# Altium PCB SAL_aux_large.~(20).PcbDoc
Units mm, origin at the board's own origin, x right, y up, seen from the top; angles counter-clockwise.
Board outline 62 x 80 mm, 2 copper layers (Top Layer, Bottom Layer); 36 components, 48 nets, 158 pads, 6 vias.
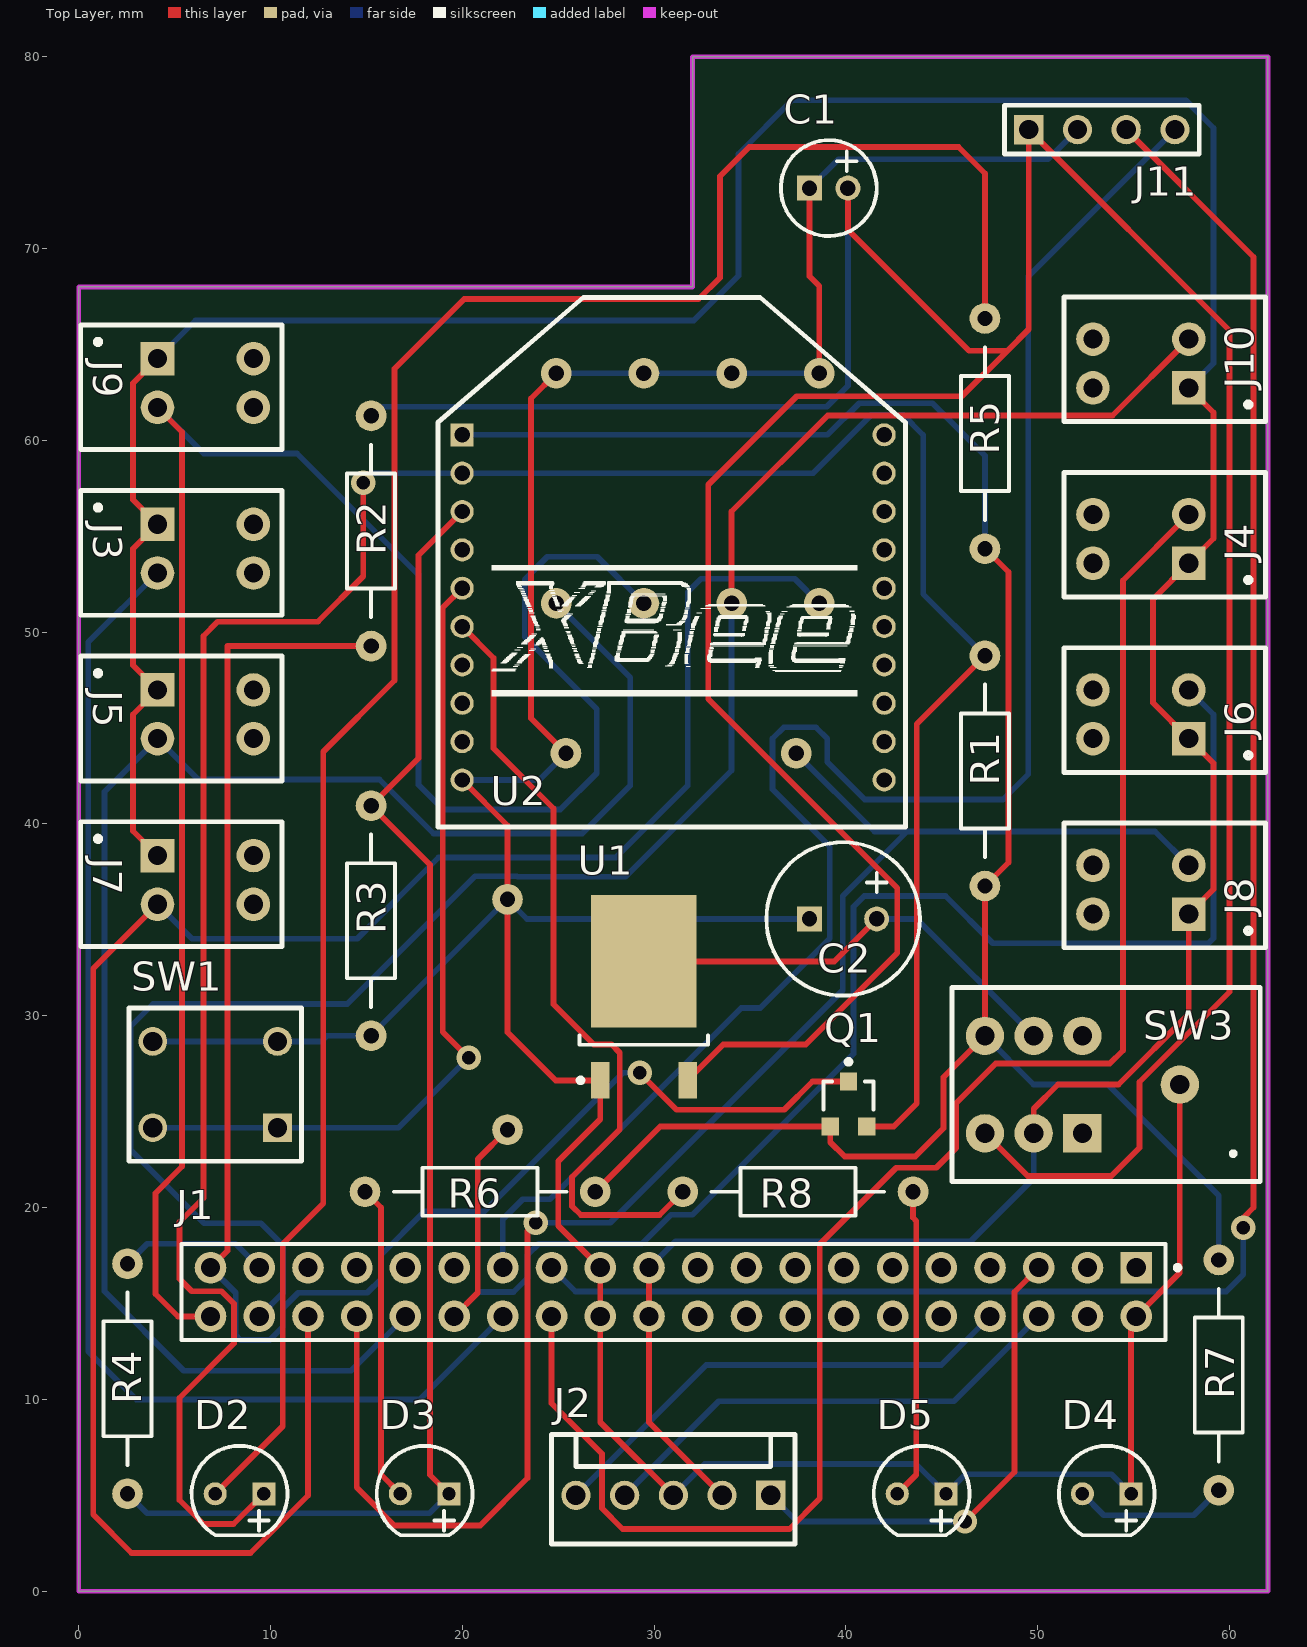
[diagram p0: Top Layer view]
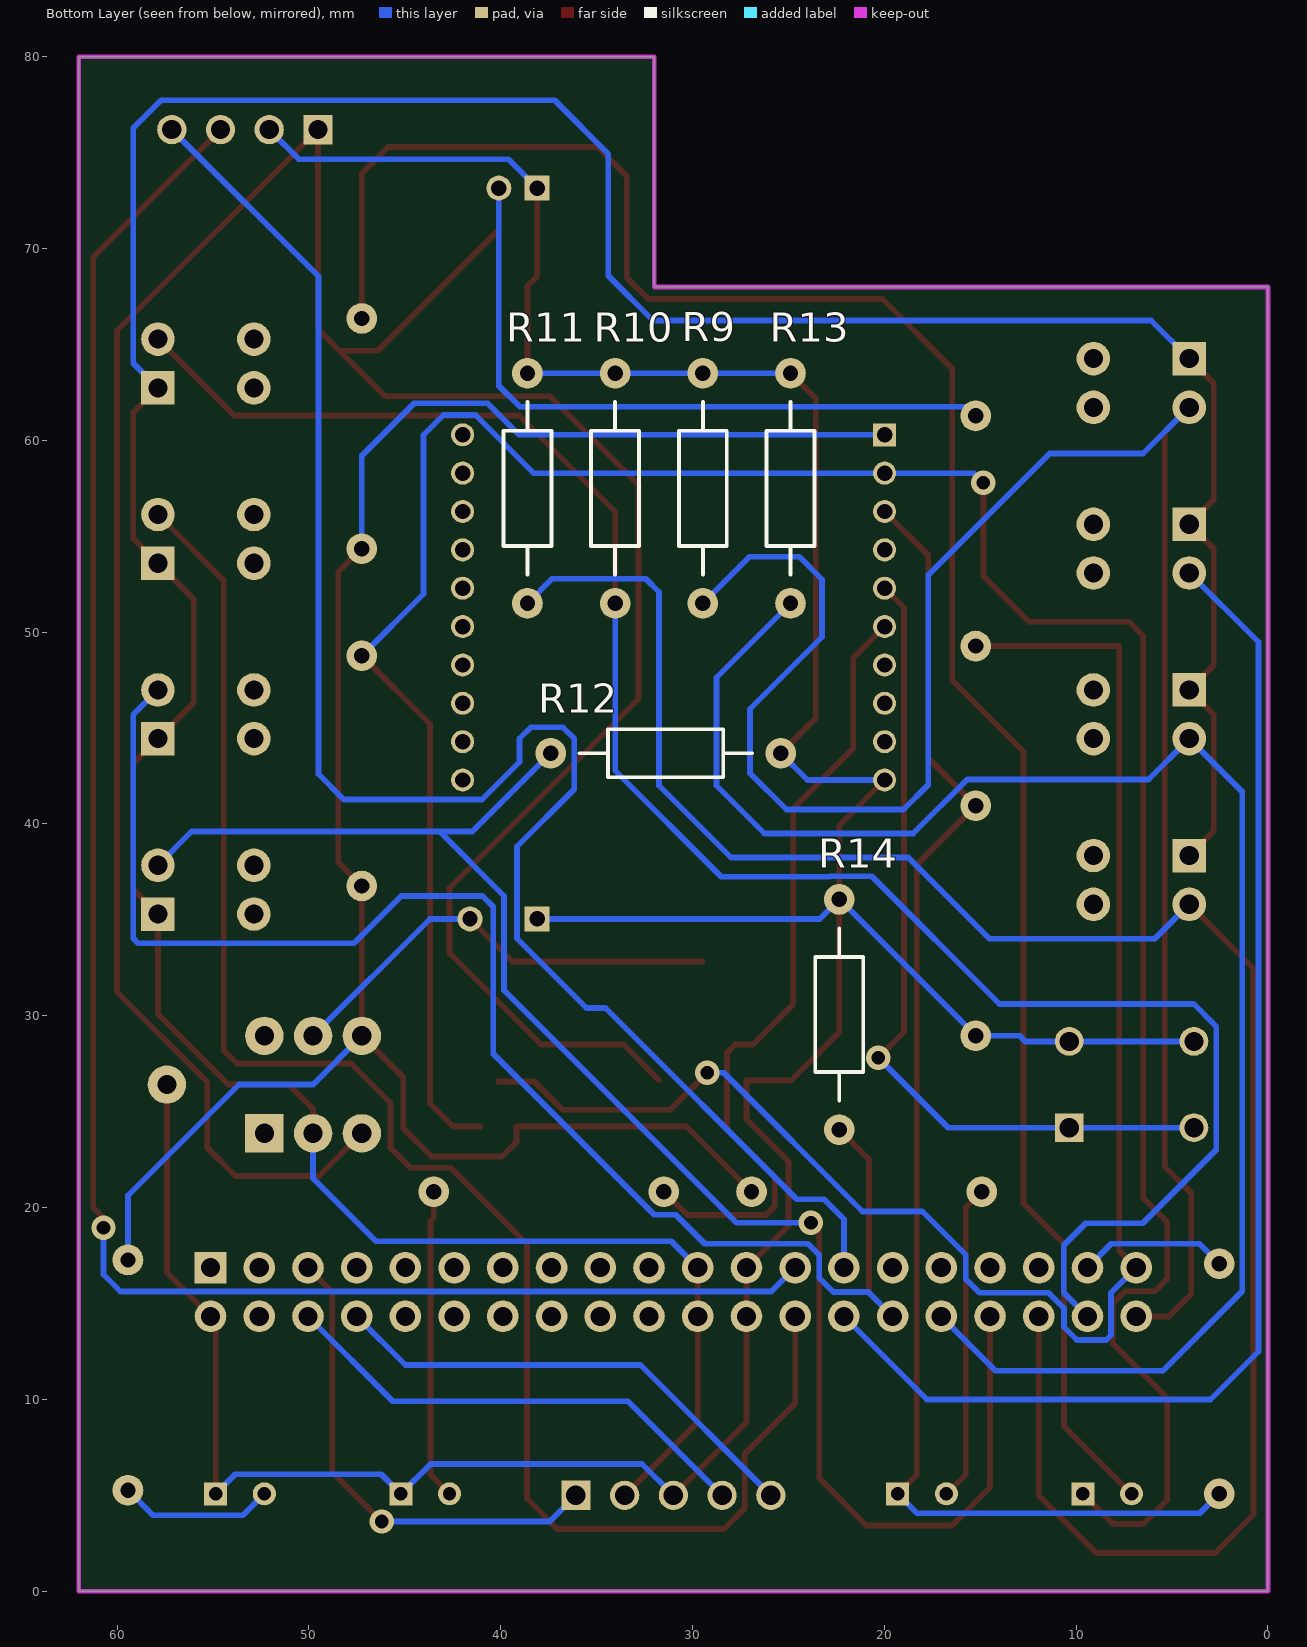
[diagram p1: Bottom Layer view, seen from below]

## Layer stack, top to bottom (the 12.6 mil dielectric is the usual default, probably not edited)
Top Layer: signal copper 0.0356
Dielectric: dielectric 0.32, FR-4, Dk 4.8
Bottom Layer: signal copper 0.0356

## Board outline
0,0 62,0 62,80 32,80 32,68 0,68

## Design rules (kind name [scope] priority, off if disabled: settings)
Clearance [All] p1: gap=0.254
PolygonConnect [All] p1: connectstyle=Relief reliefconductorwidth=0.254 reliefentries=4 polygonreliefangle="90 Angle"
RoomDefinition SAL_aux [InComponentClass('SAL_aux')] p1: confinementstyle=ConfineIn formatcopy=TRUE lockcomponents=FALSE outline 0,0 62,0 62,80 0,80
RoutingVias [All] p1: holewidth=0.711 width=1.27 viastyle="Through Hole" minholewidth=0.711 minwidth=1.27 maxholewidth=0.711 maxwidth=1.27
SilkscreenOverComponentPads [All] p1: minsilkscreentomaskgap=0.254
SolderMaskExpansion [All] p1: expansion=0.102
TestPointUsage [All] p1: valid=0 allowmultiple=FALSE
Testpoint [All] p1: side=15 testpointundercomponent=TRUE minsize=1.016 maxsize=2.54 preferedsize=1.524 minholesize=0 maxholesize=1.016 preferedholesize=0.813 testpointgrid=0.025 style=1023 order=0123456789
Width [All] p1: maxlimit=1 minlimit=0.254 preferedwidth=0.3 checkconnectedcopper=TRUE
23 further rules are at their usual default settings.

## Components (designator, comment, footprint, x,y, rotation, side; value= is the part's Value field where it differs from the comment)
C1 "10 uF" "PANASONIC ECA1HAM100X" 38.1,73.152 r0 top
C2 "100 uF" "PANASONIC ECA1HAM101X" 38.1,35.052 r0 top
D2 "Yellow" "VISHAY TLLR4401" 7.112,5.08 r0 top
D3 "Red" "VISHAY TLLR4401" 16.764,5.08 r0 top
D4 "Green" "VISHAY TLLR4401" 52.324,5.08 r0 top
D5 "Blue" "VISHAY TLLR4401" 42.672,5.08 r0 top
J1 "SSW-120-01-G-D" "SAMTEC SSW-120-1-G-D" 31,15.6 r180 top
J2 "I2C Connector" "TYCO 640456-5" 31,5 r0 top
J3 "WAGO 234-502" "WAGO 234-502" 6.604,54.356 r270 top
J4 "WAGO 234-502" "WAGO 234-502" 55.372,54.864 r90 top
J5 "WAGO 234-502" "WAGO 234-502" 6.604,45.72 r270 top
J6 "WAGO 234-502" "WAGO 234-502" 55.372,45.72 r90 top
J7 "WAGO 234-502" "WAGO 234-502" 6.604,37.084 r270 top
J8 "WAGO 234-502" "WAGO 234-502" 55.372,36.576 r90 top
J9 "WAGO 234-502" "WAGO 234-502" 6.604,62.992 r270 top
J10 "WAGO 234-502" "WAGO 234-502" 55.372,64.008 r90 top
J11 "TSW-104-07-G-S" "SAMTEC TSW-104-XX-X-S" 53.34,76.2 r0 top
Q1 "BSS138" SOT23 40.132,25.4 r0 top
R1 "10K" Resistência 47.244,48.768 r270 top
R2 "10K" Resistência 15.24,49.276 r90 top
R3 "10K" Resistência 15.24,28.956 r90 top
R4 "10K" Resistência 2.54,5.08 r90 top
R5 "1K" Resistência 47.244,54.356 r90 top
R6 "1K" Resistência 26.924,20.828 r180 top
R7 "1K" Resistência 59.436,17.272 r270 top
R8 "1K" Resistência 31.496,20.828 r0 top
R9 "10K" Resistência 29.464,63.5 r270 bottom
R10 "10K" Resistência 34.036,63.5 r270 bottom
R11 "10K" Resistência 38.608,63.5 r270 bottom
R12 "10K" Resistência 25.4,43.688 r0 bottom
R13 "10K" Resistência 24.892,63.5 r270 bottom
R14 "10K" Resistência 22.352,36.068 r270 bottom
SW1 "OMRON B3F-1002" "OMRON B3F-1002" 7.112,26.416 r0 top
SW3 "MULTICOMP 2AD1T2A2M7RE" "MULTICOMP 2AD1T2A2M7RE" 49.784,26.416 r90 top
U1 "LM1117DT-3.3" TD03B_N 29.464,30.988 r90 top
U2 "XBee" XBee 30.988,50.292 r0 top

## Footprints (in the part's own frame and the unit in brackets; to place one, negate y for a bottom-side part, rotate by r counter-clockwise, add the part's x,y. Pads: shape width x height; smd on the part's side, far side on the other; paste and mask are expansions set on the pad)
"MULTICOMP 2AD1T2A2M7RE" [mm] "Switch, DPDT ON-ON"
  rect 2x2 hole 1: 1(-2.54,-2.54)
  round 2 hole 1: 2(-2.54,0) 3(-2.54,2.54) 4(2.54,-2.54) 5(2.54,0) 6(2.54,2.54) GND(0,-7.62)
  silkscreen extent -5.06,-11.81 5.05,4.25
"OMRON B3F-1002" [mm] "6.0mm Tactil Switch"
  rect 1.5x1.5 hole 1: 1(3.25,-2.25)
  round 1.5 hole 1: 2(-3.25,-2.25) 3(3.25,2.25) 4(-3.25,2.25)
  silkscreen extent -4.5,-4 4.5,4
"PANASONIC ECA1HAM100X" [mm]
  rect 1.3x1.3 hole 0.8: 1(0,0)
  round 1.3 hole 0.8: 2(2,0)
  silkscreen extent -1.5,-2.5 3.5,2.5
"PANASONIC ECA1HAM101X" [mm]
  rect 1.3x1.3 hole 0.8: 1(0,0)
  round 1.3 hole 0.8: 2(3.5,0)
  silkscreen extent -2.25,-4 5.75,4
Resistência [mm]
  round 1.6 hole 0.8: 1(0,0) 2(12,0)
  silkscreen extent 1.5,-1.25 10.5,1.25
"SAMTEC SSW-120-1-G-D" [mm]
  rect 1.65x1.65 / inner round 1.65 / far side rect 1.65x1.65 hole 1 mask+0: 1(-24.13,-1.27)
  round 1.65 hole 1 mask+0: 2(-24.13,1.27) 3(-21.59,-1.27) 4(-21.59,1.27) 5(-19.05,-1.27) 6(-19.05,1.27) 7(-16.51,-1.27) 8(-16.51,1.27) 9(-13.97,-1.27) 10(-13.97,1.27) 11(-11.43,-1.27) 12(-11.43,1.27) 13(-8.89,-1.27) 14(-8.89,1.27) 15(-6.35,-1.27) 16(-6.35,1.27) 17(-3.81,-1.27) 18(-3.81,1.27) 19(-1.27,-1.27) 20(-1.27,1.27) 21(1.27,-1.27) 22(1.27,1.27) 23(3.81,-1.27) 24(3.81,1.27) 25(6.35,-1.27) 26(6.35,1.27) 27(8.89,-1.27) 28(8.89,1.27) 29(11.43,-1.27) 30(11.43,1.27) 31(13.97,-1.27) 32(13.97,1.27) 33(16.51,-1.27) 34(16.51,1.27) 35(19.05,-1.27) 36(19.05,1.27) 37(21.59,-1.27) 38(21.59,1.27) 39(24.13,-1.27) 40(24.13,1.27)
  silkscreen extent -26.41,-2.5 25.65,2.5
"SAMTEC TSW-104-XX-X-S" [mil] "4 pin 2.54mm pitch header"
  rect 60x60 hole 39.37: 1(-150,0)
  round 60 hole 39.37: 2(-50,0) 3(50,0) 4(150,0)
  silkscreen extent -200,-50 200,50
SOT23 [mm] "SOT-23; 3 Leads; Body 3.1 x 2.5 mm, inc. leads (LxW max), Alternate Lead Configuration"
  rect 0.9x0.95 smd: 1(0,1.175) 2(0.95,-1.175) 3(-0.95,-1.175)
  silkscreen extent -1.3,-0.3 1.3,2.32
TD03B_N [mm] "D-PAK, 4-Leads, Body 6.1x6.6mm, Pitch 2.29mm, Lead Span 9.7mm, IPC Medium Density"
  rect 1.9x0.95 smd: 1(-4.35,2.28) 3(-4.35,-2.28)
  rect 6.9x5.5 smd: 4(1.85,0)
  silkscreen extent -4.47,-3.35 -2,3.43
"TYCO 640456-5" [mil] "I2C Connector"
  rect 60x60 hole 40.16: 1(200,0)
  round 60 hole 40.16: 2(100,0) 3(0,0) 4(-100,0) 5(-200,0)
  silkscreen extent -250,-100 250,125
"VISHAY TLLR4401" [mm] "3mm LED"
  round 1.2 hole 0.7: 1(0,0)
  rect 1.2x1.2 hole 0.7: 2(2.54,0)
  silkscreen extent -1.23,-2.17 3.77,2.5
"WAGO 234-502" [mm]
  rect 1.75x1.75 hole 1: 1(-1.27,-2.5)
  round 1.75 hole 1: 2(-1.27,2.5) 3(1.27,-2.5) 4(1.27,2.5)
  silkscreen extent -3.03,-6.5 3.47,4
XBee [mm] "ZigBee device"
  rect 1.2x1.2 hole 0.8: 1(-11,10)
  round 1.2 hole 0.8: 2(-11,8) 3(-11,6) 4(-11,4) 5(-11,2) 6(-11,0) 7(-11,-2) 8(-11,-4) 9(-11,-6) 10(-11,-8) 11(11,-8) 12(11,-6) 13(11,-4) 14(11,-2) 15(11,0) 16(11,2) 17(11,4) 18(11,6) 19(11,8) 20(11,10)
  silkscreen extent -12.26,-10.44 12.12,17.17

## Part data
C1: library part "PANASONIC ECA1HAM100X"
C2: library part "PANASONIC ECA1HAM101X"
D2 D3 D4 D5: library part "VISHAY TLLG4401", "Green LED PCB 3mm"
J1: library part "SAMTEC SSW-120-01-G-D"
J2: library part "TYCO 640456-5"
J11: library part "SAMTEC TSW-104-07-G-S", "4 pin 2.54mm pitch header"
Q1: "N-Channel Enhancement Mode Vertical DMOS FET"
R1 R2 R3 R4 R5 R6 R7 R8 R9 R10 R11 R12 R13 R14: library part Resistência
SW1: "6.0mm Tact Switch"
U1: "800mA Low-Dropout Linear Regulator"

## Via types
v1: diameter 1.27, hole 0.711, Top Layer to Bottom Layer, 6 vias

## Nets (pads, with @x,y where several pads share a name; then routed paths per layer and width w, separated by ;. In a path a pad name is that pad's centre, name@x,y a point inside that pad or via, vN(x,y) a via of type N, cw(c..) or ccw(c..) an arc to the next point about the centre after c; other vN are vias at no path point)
3.3V: Q1.3 R1.2 R5.1 R6.1 R7.1 SW3.6 U2.1 | length 106.4
  Top Layer w0.3: R6.1 30.321,24.225 Q1.3 39.182,23.411 39.932,22.661 43.615,22.661 45.088,24.134 45.088,26.8 SW3.6 R1.2 48.466,37.99 48.466,53.134 R5.1
  Bottom Layer w0.3: U2.1 39.042,60.292 40.689,61.939 44.504,61.939 47.244,59.199 R5.1 ; SW3.6 49.78,26.42 53.648,26.42 59.436,20.632 R7.1
"3.3V OUT": C2.2 SW3.5 U1.4 | length 23.8
  Top Layer w0.3: U1.4 39.386,32.838 C2.2
  Bottom Layer w0.3: C2.2 43.688,35.052 SW3.5
/INT: J1.20
/RESET: J1.5 J2.1 | length 25.5
  Top Layer w0.3: v1(46.206,3.636) 48.78,6.21 48.78,15.6 J1.5
  Bottom Layer w0.3: J2.1 37.444,3.636 v1(46.206,3.636)
A0: J1.7
A4/LSDA: J1.1
A5/LSCL: J1.3
B5: J1.10
C0: J1.25 J11.3 | length 99.6
  Top Layer w0.3: J11.3 61.25,69.56 61.25,20 60.709,19.459 v1(60.709,18.952)
  Bottom Layer w0.3: J1.25 25.895,15.625 59.82,15.625 60.709,16.514 v1(60.709,18.952)
C1: J1.27 J11.4 | length 90.5
  Bottom Layer w0.3: J1.27 22.11,19.395 23.147,20.431 24.569,20.431 34.543,30.405 35.535,30.405 39.154,34.024 39.154,38.831 36.173,41.812 36.173,44.454 36.757,45.038 38.433,45.038 39.018,44.454 39.018,43.235 40.973,41.279 48.187,41.279 49.508,42.6 49.508,68.558 J11.4
C2: J1.29
C5: J1.35
D0: J1.40 J9.3 R9.2 | length 108.8
  Top Layer w0.3: J9.3 5.388,60.438 5.388,22.138 4,20.75 4,15.5 5.17,14.33 J1.40
  Bottom Layer w0.3: J9.3 6.513,59.313 11.382,59.313 17.707,52.988 17.707,42.043 19,40.75 25.103,40.75 27,42.647 27,46 23.25,49.75 23.25,52.75 24.428,53.928 27.036,53.928 R9.2
D1: J1.38 J10.3 R10.2 | length 98.6
  Top Layer w0.3: R10.2 34.036,56.287 39.045,61.296 53.89,61.296 J10.3
  Bottom Layer w0.3: J1.38 10.646,15.566 10.646,18.038 9.503,19.181 6.531,19.181 2.696,23.016 2.696,29.443 3.864,30.611 13.999,30.611 20.66,37.272 22.851,37.272 22.873,37.25 28.5,37.25 34.036,42.786 R10.2
D2: J1.36 J7.3 R11.2 | length 105.3
  Top Layer w0.3: J7.3 0.75,32.46 0.75,4 2.75,2 8.959,2 11.95,4.991 J1.36
  Bottom Layer w0.3: J7.3 5.903,34.015 14.515,34.015 18.75,38.25 28,38.25 31.75,42 31.75,52.096 32.439,52.785 37.323,52.785 R11.2
D3: J1.34 J8.3 R12.2 | length 99.7
  Top Layer w0.3: J1.34 14.49,5.405 16.462,3.433 20.933,3.433 23.397,5.897 23.397,18.775 v1(23.828,19.206)
  Bottom Layer w0.3: v1(23.828,19.206) 27.706,19.206 39.83,31.33 39.83,36.25 43.183,39.603 ; R12.2 41.485,39.603 43.183,39.603 ; J8.3 56.115,39.603 ; 43.183,39.603 56.115,39.603 ; 43.183,39.603 56.115,39.603
D4: J1.32 J5.3 R13.2 | length 87.4
  Bottom Layer w0.3: J1.32 14.2,11.5 5.474,11.5 1.336,15.638 1.336,41.682 J5.3 6.234,42.32 15.68,42.32 18.5,39.5 26.25,39.5 28.75,42 28.75,47.642 R13.2
D5: J1.30 J6.3 R14.2 | length 79.4
  Top Layer w0.3: J1.30 20.806,15.566 20.806,22.522 R14.2
  Bottom Layer w0.3: J1.30 20.84,15.6 22.66,15.6 23.397,16.336 23.397,17.53 23.981,18.114 29.364,18.114 30.874,19.624 31.995,19.624 40.389,28.018 40.389,35.691 40.948,36.25 45.19,36.25 47.654,33.786 58.906,33.786 59.16,34.04 59.16,45.702 J6.3
D6: J1.28 J3.3 | length 66.5
  Bottom Layer w0.3: J3.3 0.5,49.482 0.5,12.5 3,10 17.78,10 J1.28
D7: J1.26 J4.3 | length 87.5
  Top Layer w0.3: J1.26 24.65,9.8 27.283,7.167 27.283,4.322 28.355,3.25 37.057,3.25 38.637,4.83 38.637,18.089 42.624,22.077 44.707,22.077 45.749,23.118 45.749,25.455 47.806,27.512 53.75,27.512 54.435,28.198 54.435,52.697 J4.3
DIN: D3.2 R3.2 R4.1 U2.3 | length 72.5
  Top Layer w0.3: D3.2 18.317,6.067 18.317,37.879 R3.2 17.707,43.423 17.707,54.011 U2.3
  Bottom Layer w0.3: R4.1 3.552,4.068 18.292,4.068 D3.2
DOUT: D2.2 Q1.2 R1.1 U2.2 | length 140.8
  Top Layer w0.3: D2.2 8.072,3.5 6.5,3.5 5.25,4.75 5.25,10.077 8.099,12.926 8.099,14.99 7.448,15.641 5.896,15.641 5.25,16.287 5.25,19.25 6.5,20.5 6.5,49.808 7.242,50.55 12.475,50.55 14.837,52.912 v1(14.837,57.789) ; Q1.2 42.487,24.225 43.691,25.429 43.691,45.215 R1.1
  Bottom Layer w0.3: v1(14.837,57.789) 15.34,58.292 U2.2 38.292,58.292 41.32,61.32 42.98,61.32 44.021,60.278 44.021,51.991 R1.1
EYEB: J1.19
EYEF: J1.9
EYEL: J1.13
EYER: J1.11
NetD2_1: D2.1 R5.2 | length 109.3
  Top Layer w0.3: D2.1 10.639,8.607 10.639,18.099 12.75,20.21 12.75,43.764 16.462,47.477 16.462,63.733 20.095,67.365 32.312,67.365 33.43,68.482 33.43,73.766 34.954,75.29 45.872,75.29 47.244,73.918 R5.2
NetD3_1: D3.1 R6.2 | length 16.5
  Top Layer w0.3: R6.2 15.751,20.001 15.751,6.093 D3.1
NetD4_1: D4.1 R7.2 | length 8.1
  Bottom Layer w0.3: D4.1 53.438,3.966 58.13,3.966 R7.2
NetD5_1: D5.1 R8.2 | length 16.2
  Top Layer w0.3: D5.1 43.666,6.074 43.666,19.308 43.496,19.478 R8.2
PWM1/SERVOR: J1.18
PWM2/SERVOL: J1.16
PWM3: J1.14
PWM4: J1.12
RESET: SW1.1 SW1.2 U2.5 | length 43.4
  Top Layer w0.3: U2.5 18.977,51.281 18.977,29.163 v1(20.323,27.817)
  Bottom Layer w0.3: SW1.2 SW1.1 16.672,24.166 v1(20.323,27.817)
RSSI: R8.1 U2.6 | length 41.7
  Top Layer w0.3: U2.6 21.619,48.661 21.619,43.946 24.75,40.815 24.75,30.604 26.854,28.5 27.768,28.5 28.2,28.069 28.2,24.074 25.72,21.594 25.72,20.07 26.177,19.613 30.281,19.613 R8.1
RX: J1.39 Q1.1 R2.1 | length 84.9
  Top Layer w0.3: J1.39 7.75,17.75 7.75,49.276 R2.1 ; v1(29.239,27.03) 31.169,25.099 36.78,25.099 38.256,26.575 Q1.1
  Bottom Layer w0.3: J1.39 8.181,15.559 8.181,13.356 8.436,13.101 9.96,13.101 10.639,13.78 10.639,14.757 11.441,15.559 15.04,15.559 15.751,16.27 15.751,17.53 18.015,19.794 21.142,19.794 28.378,27.03 v1(29.239,27.03)
SCL: J1.31
SDA: J1.33
TX: J1.37 R4.2 | length 7.8
  Bottom Layer w0.3: R4.2 3.574,18.114 8.166,18.114 J1.37
US_B: J1.17
US_F: J1.15
V+: J1.4
VDD: J1.21 J1.22 J2.2 J3.1 J4.1 J5.1 J6.1 J7.1 J8.1 J9.1 J10.1 SW3.2 | length 193.6
  Top Layer w0.3: J7.1 2.823,39.635 2.823,45.709 J5.1 2.823,48.271 2.823,54.345 J3.1 2.823,56.907 2.823,62.981 J9.1 ; J1.21 J1.22 29.73,8.81 J2.2 ; SW3.2 49.784,25.15 51.054,26.42 54.207,26.42 57.872,30.085 J8.1 59.16,36.594 59.16,43.162 J6.1 56,46.322 56,51.722 J4.1 59.16,54.882 59.16,61.45 J10.1
  Bottom Layer w0.3: J9.1 6.092,66.25 32.061,66.25 34.395,68.584 34.395,74.934 37.189,77.728 57.712,77.728 59.16,76.28 59.16,64.026 J10.1 ; J1.21 31.11,18.25 46.5,18.25 49.784,21.534 SW3.2
"VDD OUT": C1.2 J11.1 R2.2 SW3.3 U1.3 | length 192.1
  Top Layer w0.3: U1.3 33.606,28.5 37.897,28.5 42.675,33.278 42.675,36.656 32.82,46.511 32.82,57.684 37.432,62.296 46.036,62.296 48.412,64.672 ; C1.2 40.1,70.981 46.409,64.672 48.412,64.672 ; SW3.3 49.475,21.645 53.826,21.645 55.299,23.118 55.299,26.547 60,31.248 60,65.73 J11.1 49.53,65.79 ; 48.412,64.672 49.53,65.79 ; 48.412,64.672 49.53,65.79
  Bottom Layer w0.3: R2.2 15.714,61.75 39,61.75 40.1,62.85 C1.2
VSS: C1.1 C2.1 D4.2 D5.2 J1.2 J1.23 J1.24 J2.3 J11.2 R3.1 R9.1 R10.1 R11.1 R12.1 R13.1 R14.1 SW1.3 SW1.4 SW3.GND U1.1 U2.10 | length 197.1
  Top Layer w0.3: U2.10 22.352,39.928 R14.1 22.352,29.141 24.87,26.623 U1.1@27.184,26.623 ; R13.1 23.574,62.182 23.574,45.514 R12.1 ; J2.3 27.19,8.81 J1.24 J1.23 25,19.06 25,22.42 27.184,24.604 U1.1@27.184,26.623 ; C1.1 38.1,68.559 38.608,68.051 R11.1 ; D4.2 54.864,14.064 J1.2 57.404,16.604 SW3.GND ; U1.1@27.184,26.623 U1.1 U1.1@27.184,26.623
  Bottom Layer w0.3: SW1.4 SW1.3 12.652,28.666 12.942,28.956 R3.1 15.24,28.978 22.33,36.068 R14.1 23.368,35.052 C2.1 ; U2.10 24.004,42.292 R12.1 ; R13.1 R9.1 R10.1 R11.1 ; J2.3 32.638,6.638 43.654,6.638 D5.2 46.232,6.1 53.844,6.1 D4.2 ; C1.1 39.603,74.655 50.525,74.655 J11.2
XAXIS: J1.8 J2.5 | length 25.5
  Bottom Layer w0.3: J2.5 32.71,11.79 44.97,11.79 J1.8
YAXIS: J1.6 J2.4 | length 25.5
  Bottom Layer w0.3: J2.4 33.37,9.91 45.63,9.91 J1.6
pads on no net: J3.2 J3.4 J4.2 J4.4 J5.2 J5.4 J6.2 J6.4 J7.2 J7.4 J8.2 J8.4 J9.2 J9.4 J10.2 J10.4 SW3.1 SW3.4 U2.4 U2.7 U2.8 U2.9 U2.11 U2.12 U2.13 U2.14 U2.15 U2.16 U2.17 U2.18 U2.19 U2.20

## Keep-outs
Keep-Out Layer:
  the board outline again, w0.254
